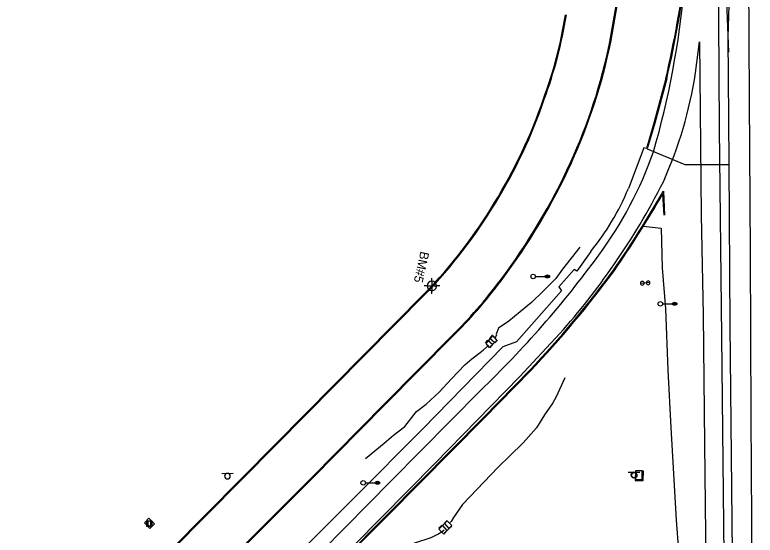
# Model space of a CAD drawing. Extents: x 2145380 to 2156929, y 139568 to 149130.
# Drawn here: x 2150285.2 to 2150778, y 143433.2 to 143779.3 of the extents above; entities that cross this region are included whole.
import ezdxf

# ---------------------------------------------------------------- set-up
doc = ezdxf.new("R2010")
doc.units = 0
for name, color, linetype in [('Default', 7, 'Continuous'), ('SURV_Benchmark', 7, 'Continuous'), ('SURV_Text', 7, 'Continuous'), ('TOPO_Asphalt', 7, 'Continuous'), ('TOPO_Concrete', 7, 'Continuous'), ('TOPO_Curb Back', 7, 'Continuous'), ('TOPO_DRAIN_Headwall', 7, 'Continuous'), ('TOPO_Flowline', 7, 'Continuous'), ('TOPO_Light Pole', 7, 'Continuous'), ('TOPO_Misc', 7, 'Continuous'), ('TOPO_Sign', 7, 'Continuous'), ('TOPO_Wall Freestanding', 7, 'Continuous')]:
    doc.layers.add(name, color=color, linetype=linetype)

# ---------------------------------------------------------------- blocks, each defined once
blk = doc.blocks.new('LP')
at = {"layer": 'TOPO_Light Pole'}
blk.add_line((3.8, 0), (20.3, 0), dxfattribs=at)
for points in [[(20.3, 0), (27.9, 0)], [(20.3, 0), (23.5, 0)], [(20.8, 1.3), (27.4, 1.3)], [(20.8, 1.3), (23.5, 1.3)], [(23.7, 1.3), (27.4, 1.3)], [(23.7, 0), (27.9, 0)], [(20.8, -1.3), (27.4, -1.3)], [(20.8, -1.3), (23.5, -1.3)], [(23.7, -1.3), (27.4, -1.3)]]:
    blk.add_lwpolyline(points, dxfattribs=at)
blk.add_circle((0, 0), 3.81, dxfattribs=at)
blk.add_ellipse((24.1, 0), major_axis=(3.81, 0), ratio=0.666667, dxfattribs=at)
blk = doc.blocks.new('POST')
at = {"layer": 'TOPO_Misc'}
for start, end in [(90, 180), (180, 270), (360, 90), (270, 0)]:
    blk.add_arc((0, 0), 3.16, start, end, dxfattribs=at)
blk = doc.blocks.new('EXSIGN')
at = {"layer": 'Default'}
blk.add_line((9.3, 4.4), (-9.3, 4.4), dxfattribs=at)
blk.add_circle((0, 0), 4.42, dxfattribs=at)
blk = doc.blocks.new('BM')
at = {"layer": 'SURV_Benchmark'}
for p, q in [((0, 2.49), (0, 4.15)), ((-2.49, 0), (-4.16, 0)), ((4.16, 0), (2.49, 0)), ((0, -4.16), (0, -2.49))]:
    blk.add_line(p, q, dxfattribs=at)
for points in [[(-2.5, 0), (-2.49, 0), (0, 0), (0, -2.49), (0, -2.49)], [(-2.5, 0), (-2.49, 0), (0, 0), (0, -2.49), (0, -2.49)], [(0, 2.49), (0, 2.49), (0, 0), (2.49, 0), (2.49, 0), (2.49, 0)], [(0, 2.49), (0, 2.49), (0, 0), (2.49, 0), (2.49, 0), (2.49, 0), (2.49, 0)]]:
    blk.add_lwpolyline(points, dxfattribs=at)
for start, end in [(90.0638, 180.0068), (0.0638, 90.0068), (0.0638, 90.0068), (180.0638, 270.0068), (180.0638, 270.0068), (269.9472, 359.9927)]:
    blk.add_arc((0, 0), 2.5, start, end, dxfattribs=at)

msp = doc.modelspace()

# ---------------------------------------------------------------- linework, layer by layer
at = {"layer": 'TOPO_Asphalt'}
for points in [[(2150772.83, 143886.16), (2150773.51, 143803.73), (2150773.92, 143723.32), (2150774.62, 143621.07), (2150775.2, 143512.02), (2150776.06, 143373.6), (2150776.8, 143240.22), (2150777.68, 143101.35), (2150778.04, 143055.61)], [(2150761.33, 143058.39), (2150760.85, 143109.01), (2150759.25, 143261.24), (2150757.66, 143398.88), (2150755.78, 143565.43), (2150754.21, 143703.67), (2150753.32, 143849.02), (2150753.42, 143879.74)], [(2150738.39, 143740.69), (2150740.91, 143761.3), (2150741.44, 143715.51), (2150742.16, 143646.15), (2150743.31, 143579.69), (2150744.37, 143494.08), (2150745.11, 143413.41), (2150746.4, 143303.44), (2150747.21, 143203.09)], [(2150705.59, 143690.44), (2150703.88, 143690.9), (2150693.64, 143663.88)], [(2150706.16, 143690.28), (2150731.1, 143679.69), (2150760.66, 143679.73)], [(2150703.54, 143638.66), (2150715.43, 143637.38), (2150716.04, 143611.08), (2150718.3, 143583.81), (2150719.91, 143543.04), (2150721.86, 143504.76), (2150725.48, 143443.24), (2150730, 143381.98), (2150732.94, 143323.43), (2150732.64, 143295.69), (2150731.97, 143292.82), (2150731.53, 143291.4), (2150731.28, 143291.38), (2150723.93, 143305.15), (2150720.58, 143310.57)], [(2150668.57, 143621.97), (2150659.27, 143608.84), (2150657.46, 143609.97), (2150647.36, 143598.36), (2150648.99, 143595.75), (2150619.05, 143561.87), (2150610.1, 143558.45), (2150556.8, 143503.95), (2150510.88, 143457.93), (2150447.76, 143394.58), (2150380.77, 143325.24), (2150333.55, 143277.1), (2150301.88, 143246.6)], [(2150384.03, 143298.54), (2150425.42, 143340.22), (2150493.57, 143408.83), (2150564.76, 143480.95), (2150621.11, 143538.46), (2150647.96, 143567.36)], [(2150595.02, 143529.26), (2150535.74, 143469.27), (2150474.56, 143407.41), (2150404.3, 143336.17), (2150333.15, 143265.12)]]:
    msp.add_lwpolyline(points, dxfattribs=at)
for centre, radius, start, end in [((2150165.26, 143846.68), 567.61, 343.7795, 355.024), ((2150454.44, 143785.55), 287.47, 335.932, 351.0219), ((2150465.86, 143773.59), 258.92, 323.4574, 340.7276), ((2150309.88, 143873.91), 456.02, 325.0986, 333.2016), ((2150541.94, 143726.15), 163.98, 320.5546, 337.6835), ((2150114.89, 144028.81), 692.87, 313.86438, 323.78208), ((2150321.7, 143861.17), 439.05, 317.9956, 325.5793)]:
    msp.add_arc(centre, radius, start, end, dxfattribs=at)
at = {"layer": 'TOPO_Concrete'}
for points in [[(2150601.03, 143558.11), (2150599.04, 143560.67), (2150603.3, 143565.91), (2150606.13, 143562.82), (2150601.03, 143558.11)], [(2150698.3, 143476.03), (2150698.12, 143469.65), (2150703.49, 143469.5), (2150703.66, 143475.88), (2150698.3, 143476.03)], [(2150698.38, 143476.02), (2150698.42, 143470.3), (2150702.78, 143470.37), (2150702.78, 143476.04), (2150698.38, 143476.02)], [(2150375.12, 143437.69), (2150371.39, 143441.52), (2150374.48, 143444.58), (2150378.15, 143440.67), (2150375.12, 143437.69)], [(2150572.98, 143442.68), (2150567.44, 143437.18), (2150570.83, 143433.95), (2150576.08, 143439.61), (2150572.98, 143442.68)]]:
    msp.add_lwpolyline(points, dxfattribs=at)
at = {"layer": 'TOPO_Curb Back'}
for points in [[(2150681.26, 143761.28), (2150688.25, 143800.82), (2150696.26, 143863.82), (2150699.51, 143889.9), (2150704.08, 143927.64), (2150709.32, 143973.42), (2150713.36, 144009.22), (2150716.29, 144039.49), (2150720.45, 144094.42), (2150723.05, 144142.66), (2150724.57, 144175.07), (2150725.79, 144212.36), (2150726.43, 144252.04), (2150727.32, 144302.08), (2150727.39, 144340.7), (2150727.51, 144356.42), (2150726.94, 144419.58), (2150726.03, 144497.06)], [(2150681.85, 143761.17), (2150688.84, 143800.73), (2150696.86, 143863.74), (2150700.1, 143889.83), (2150704.68, 143927.57), (2150709.91, 143973.35), (2150713.96, 144009.16), (2150716.89, 144039.44), (2150721.04, 144094.38), (2150723.65, 144142.63), (2150725.16, 144175.04), (2150726.39, 144212.35), (2150727.03, 144252.03), (2150727.92, 144302.07), (2150727.99, 144340.7), (2150728.11, 144356.42), (2150727.54, 144419.59), (2150726.63, 144497.07)], [(2150718.55, 143736.88), (2150710.54, 143707.34), (2150705.58, 143690.45)], [(2150719.13, 143736.73), (2150711.12, 143707.17), (2150706.16, 143690.28)], [(2150716.91, 143662.1), (2150717.7, 143646.01)], [(2150716.41, 143660.03), (2150717.11, 143645.98)], [(2150557.93, 143593.89), (2150517.25, 143552.96), (2150458.64, 143493.8), (2150389.25, 143423.73), (2150342.93, 143377.43)], [(2150558.36, 143593.47), (2150517.67, 143552.53), (2150459.07, 143493.37), (2150389.67, 143423.31), (2150343.32, 143376.97)], [(2150279.08, 143268.84), (2150294.36, 143282.79), (2150327.85, 143316.37), (2150375.99, 143364.65), (2150422.08, 143410.84), (2150482.57, 143471.39), (2150531.19, 143520.67), (2150575.96, 143565.53)], [(2150279.48, 143268.4), (2150294.77, 143282.36), (2150328.27, 143315.95), (2150376.42, 143364.23), (2150422.5, 143410.42), (2150483, 143470.97), (2150531.61, 143520.25), (2150576.39, 143565.11)], [(2150279.28, 143200.52), (2150310.36, 143226.03), (2150356.95, 143269.81), (2150415.47, 143328.28), (2150474.35, 143387.69), (2150532.94, 143446.7), (2150596.98, 143511.27), (2150628.02, 143543.02)], [(2150279.66, 143200.06), (2150310.76, 143225.58), (2150357.36, 143269.38), (2150415.89, 143327.86), (2150474.78, 143387.27), (2150533.37, 143446.27), (2150597.41, 143510.85), (2150628.45, 143542.6)]]:
    msp.add_lwpolyline(points, dxfattribs=at)
for centre, radius, start, end in [((2150021.5, 143899.48), 715.76, 346.86941, 352.92441), ((2150021.47, 143899.49), 716.4, 346.86864, 352.9244), ((2150362.4, 143825.16), 292.93, 339.6718, 351.0176), ((2150362.4, 143825.16), 293.53, 339.6732, 351.017), ((2150315.17, 143836.19), 373.67, 335.4801, 348.4352), ((2150315.17, 143836.19), 374.27, 335.48, 348.4365), ((2150309.9, 143835.58), 345.88, 328.4241, 341.0743), ((2150309.9, 143835.58), 346.49, 328.4246, 341.0731), ((2150267.63, 143859.16), 426.46, 323.0435, 335.3223), ((2150267.63, 143859.16), 427.06, 323.0435, 335.3224), ((2150068.74, 144034.09), 747.33, 325.38555, 330.14785), ((2150068.75, 144034.08), 747.91, 325.38474, 329.99145), ((2150317.87, 143827), 334.62, 315.8412, 328.9605), ((2150317.87, 143827.01), 335.22, 315.8406, 328.9599), ((2150118.48, 144026.62), 702.5, 316.49582, 323.5822), ((2150118.49, 144026.62), 703.09, 316.49539, 323.58298), ((2150326.08, 143816.03), 353.82, 314.9302, 322.9356), ((2150326.07, 143816.03), 354.43, 314.9304, 322.9356)]:
    msp.add_arc(centre, radius, start, end, dxfattribs=at)
at = {"layer": 'TOPO_DRAIN_Headwall'}
for points in [[(2150598.56, 143561.27), (2150600.14, 143562.96), (2150603.46, 143559.96), (2150601.39, 143557.92)], [(2150606.53, 143562.84), (2150604.7, 143561.13), (2150601.39, 143564.15), (2150603.41, 143566.44)], [(2150567.54, 143438.05), (2150569.56, 143439.86), (2150572.86, 143436.35), (2150570.91, 143434.63)], [(2150576.1, 143439.13), (2150574.41, 143437.65), (2150571.14, 143441.23), (2150572.97, 143443.01)]]:
    msp.add_lwpolyline(points, dxfattribs=at)
at = {"layer": 'TOPO_Flowline'}
for points in [[(2150661.36, 143624.75), (2150649.76, 143610.09), (2150645.27, 143603.92), (2150636.94, 143595.59), (2150629.06, 143587.91), (2150614.11, 143575.5), (2150607.15, 143570.82), (2150605.63, 143566.86), (2150605.73, 143566.21), (2150604.72, 143564.16)], [(2150518.67, 143484.23), (2150531.04, 143494.37), (2150537.28, 143499.69), (2150544.73, 143505.59), (2150552.47, 143515.52), (2150559.1, 143520.35), (2150567.6, 143528.26), (2150575.86, 143537.2), (2150584.71, 143546.44), (2150589.39, 143550.51), (2150595.03, 143554.69), (2150597.19, 143556.59), (2150599.13, 143558.36), (2150600.51, 143559.61)], [(2150651.37, 143537.78), (2150645.54, 143525.14), (2150643.32, 143521.22), (2150637.73, 143513.26), (2150632.52, 143504.71), (2150623.66, 143494.63), (2150614.67, 143486.08), (2150607.01, 143478.53), (2150588.03, 143458.77), (2150583.26, 143453.63), (2150577.25, 143444.95), (2150575.56, 143442.27), (2150575.02, 143441.56)], [(2150455.03, 143356.38), (2150487.58, 143385.94), (2150495.31, 143392.42), (2150510.89, 143403.38), (2150522.94, 143414.26), (2150528.88, 143418.07), (2150537.05, 143422.28), (2150551.4, 143428.08), (2150562.22, 143431.75), (2150566.8, 143433.94), (2150569.26, 143435.56), (2150570.8, 143436.59), (2150571.04, 143436.79)]]:
    msp.add_lwpolyline(points, dxfattribs=at)
at = {"layer": 'TOPO_Misc'}
for p, q in [((2150373.6, 143442.38), (2150373.6, 143439.97)), ((2150375.67, 143439.98), (2150375.67, 143442.39))]:
    msp.add_line(p, q, dxfattribs=at)
msp.add_lwpolyline([(2150373.01, 143439.07), (2150373.01, 143442.83), (2150376.27, 143442.83), (2150376.27, 143439.07), (2150373.01, 143439.07)], dxfattribs=at)
msp.add_arc((2150374.63, 143440.79), 1.32, 218.3412, 322.0625, dxfattribs=at)
at = {"layer": 'TOPO_Sign'}
for points in [[(2150702.05, 143600.8), (2150707.92, 143601.56)], [(2150422.97, 143474.36), (2150430.46, 143474.37)], [(2150426.72, 143474.36), (2150426.72, 143474.36)], [(2150693.41, 143475.14), (2150700.9, 143475.15)], [(2150697.16, 143475.14), (2150697.16, 143475.14)], [(2150424.85, 143472.49), (2150424.85, 143472.49)], [(2150426.72, 143470.63), (2150426.72, 143470.63)], [(2150428.59, 143472.49), (2150428.59, 143472.49)], [(2150695.29, 143473.27), (2150695.29, 143473.27)], [(2150697.16, 143471.4), (2150697.16, 143471.4)], [(2150699.03, 143473.27), (2150699.03, 143473.27)]]:
    msp.add_lwpolyline(points, dxfattribs=at)
for centre, start, end in [((2150426.72, 143472.49), 90, 180), ((2150426.72, 143472.49), 360, 90), ((2150697.16, 143473.27), 90, 180), ((2150697.16, 143473.27), 360, 90), ((2150426.72, 143472.49), 180, 270), ((2150426.72, 143472.49), 270, 0), ((2150697.16, 143473.27), 180, 270), ((2150697.16, 143473.27), 270, 0)]:
    msp.add_arc(centre, 1.87, start, end, dxfattribs=at)
at = {"layer": 'TOPO_Wall Freestanding'}
msp.add_lwpolyline([(2150769.17, 143080.78), (2150767.89, 143167.61), (2150765.93, 143268.98), (2150763.03, 143421.04), (2150761.46, 143572.97), (2150760.66, 143679.73), (2150760.43, 143710.32), (2150760.15, 143764.69), (2150761.19, 143799.86), (2150760.93, 143826.74), (2150759.61, 143868.78), (2150758.64, 143826.63), (2150758.62, 143806.22), (2150758.7, 143793.94), (2150760.2, 143754.59)], dxfattribs=at)

# ---------------------------------------------------------------- block references
at = {"layer": 'SURV_Benchmark', "xscale": 1.25, "yscale": 1.25}
msp.add_blockref('BM', (2150562.84, 143599.06), dxfattribs=at)
at = {"layer": 'TOPO_Light Pole', "xscale": 0.39370000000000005, "yscale": 0.3937000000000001}
for p in [(2150630.22, 143605.33), (2150714.91, 143587.11), (2150517.11, 143468.07)]:
    msp.add_blockref('LP', p, dxfattribs=at)
at = {"layer": 'TOPO_Misc', "xscale": 0.39370000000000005, "yscale": 0.3937000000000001}
for name, p in [('POST', (2150702.88, 143600.78)), ('POST', (2150706.74, 143601.08)), ('EXSIGN', (2150697.54, 143473.11))]:
    msp.add_blockref(name, p, dxfattribs=at)

# ---------------------------------------------------------------- texts
at = {"layer": 'SURV_Text'}
msp.add_text('BM#5', height=6, rotation=257.4, dxfattribs=at).set_placement((2150555.26, 143622.36))

doc.saveas('drawing.dxf')
